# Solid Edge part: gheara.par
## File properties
Author: User
Template: Iso Metric Part.par
Last saved by: User
Revision: 4
Application: Solid Edge
Accuracy: 0.990
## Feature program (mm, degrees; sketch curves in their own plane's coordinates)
sketch for "unnamed Protrusion 1" plane through (0, 0, 0) normal (0, 0, 1) x-axis (1, 0, 0)
  arc centre (0, -42) radius 8 from (8, -42) to (-8, -42) cw
  line (-8, -42) -> (-8, -7.0253)
  arc centre (16, -7.0253) radius 24 from (-0.2416, 10.6441) to (-8, -7.0253) ccw
  line (-0.2416, 10.6441) -> (25.5077, 34.3127)
  arc centre (30.9215, 28.4228) radius 8 from (25.5077, 34.3127) to (36.3354, 22.533) cw
  line (10.5861, -1.1355) -> (36.3354, 22.533)
  arc centre (16, -7.0253) radius 8 from (8, -7.0253) to (10.5861, -1.1355) cw
  line (8, -42) -> (8, -7.0253)
extrude "unnamed Protrusion 1" add finite 6 along -normal
sketch for "ExtrudedCutout_1" plane through (15.4608, -6.7886, 0) normal (0, 0, 1) x-axis (0.736227, 0.676734, 0)
  line (-24.8596, 7.6226) -> (-13.08, -3.2052)
extrude "ExtrudedCutout_1" cut finite 3 along -normal
sketch for "ExtrudedCutout_2" plane through (0, -34, -3) normal (0, 0, 1) x-axis (1, 0, 0)
  circle centre (0, -8) radius 3.5
extrude "ExtrudedCutout_2" cut finite 114 along -normal
sketch for "unnamed Cutout 1" plane through (15.4608, 9.2114, 0) normal (0, 0, 1) x-axis (1, 0, 0)
  circle centre (17.9297, 10.6147) radius 2.5
extrude "unnamed Cutout 1" cut through along -normal
pattern "Pattern_1" of "unnamed Cutout 1" along a curve  XDirOffset = 10 mm; XDirCount = 3; XDirSpacing = 12.4873 mm
extrude "unnamed Cutout 2" cut through
extrude "unnamed Cutout 3" cut through
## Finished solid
Body 1: solid body, 19 faces, 50 edges, 32 vertices.
  Faces by surface: plane 11, cylinder 8
  Edges by curve: line 34, circle 16
Bounding box of the edges (mm): 46.922 x 86.423 x 6.000, from (-8, -50, -6) to (38.9215, 36.4228, 0).
Cylindrical faces by radius (mm): R2.5 x3, R3.5 x1, R8 x3, R24 x1
Planar faces by outward normal: +x 1, +z 2, -x 1, -y 1, -z 1, oblique 5
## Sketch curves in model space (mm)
circle centre (33.3905, 19.8261, 0) radius 2.5
line (0, -50, 0) -> (0, 0, 0)
line (0, 0, 0) -> (36.8114, 33.8367, 0)
arc centre (30.9215, 28.4228, 0) radius 8 from (25.5077, 34.3127, 0) through (36.9692, 33.6598, 0) to (36.3354, 22.533, 0)
line (10.5861, -1.1355, 0) -> (36.3354, 22.533, 0)
arc centre (16, -7.0253, 0) radius 8 from (8, -7.0253, 0) through (8.675, -3.8091, 0) to (10.5861, -1.1355, 0)
line (8, -42, 0) -> (8, -7.0253, 0)
arc centre (0, -42, 0) radius 8 from (8, -42, 0) through (-0.2371, -49.9965, 0) to (-8, -42, 0)
line (-8, -42, 0) -> (-8, -7.0253, 0)
arc centre (16, -7.0253, 0) radius 24 from (-0.2416, 10.6441, 0) through (-5.975, 2.6235, 0) to (-8, -7.0253, 0)
line (-0.2416, 10.6441, 0) -> (25.5077, 34.3127, 0)
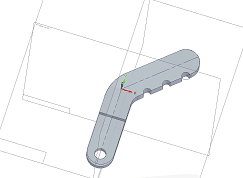
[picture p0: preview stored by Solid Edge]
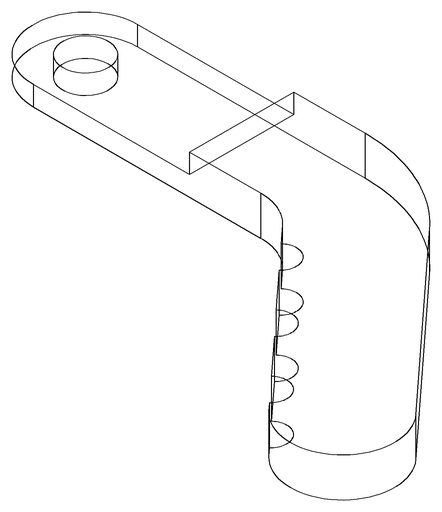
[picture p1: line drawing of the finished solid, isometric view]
